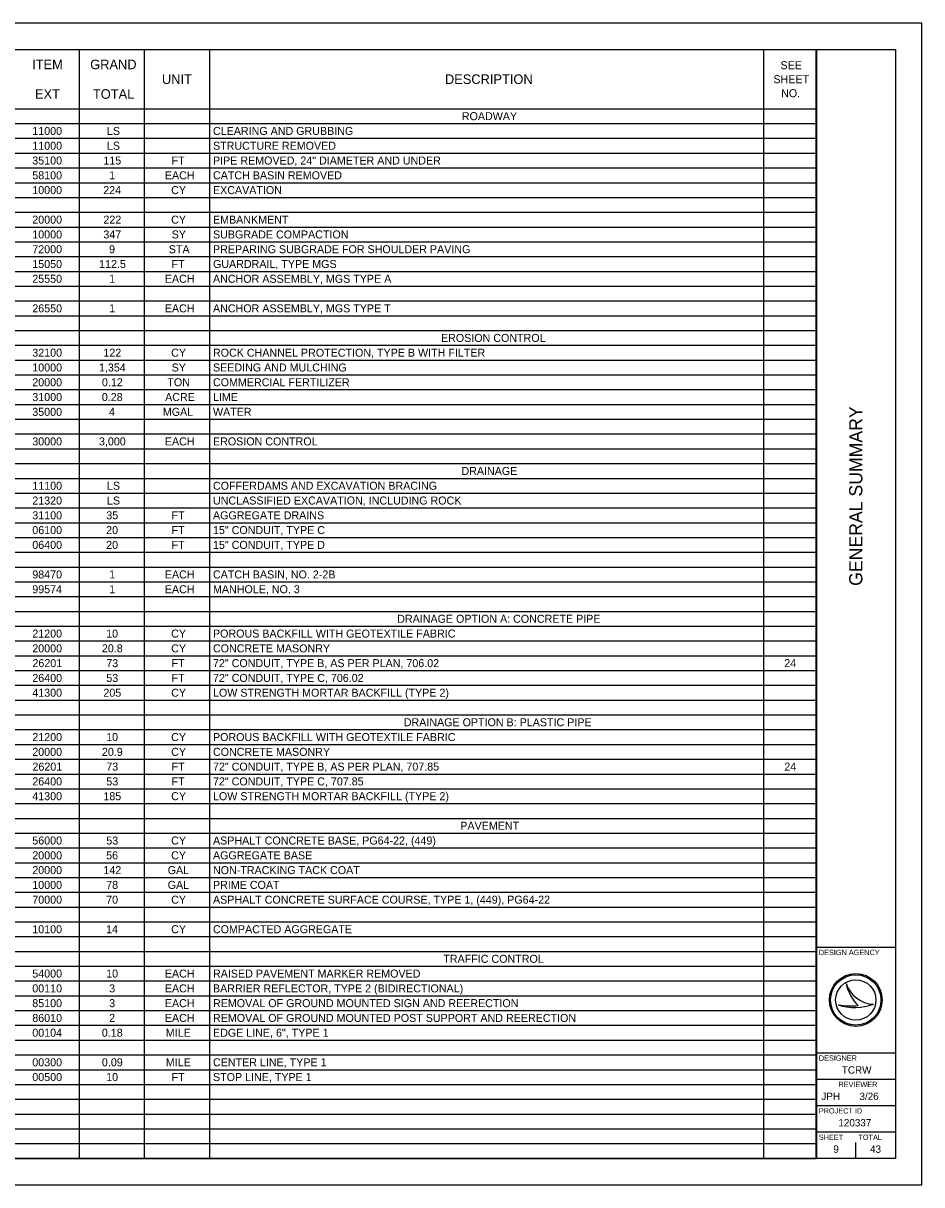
# Model space of a CAD drawing. Extents: x 0 to 34, y 0 to 35.
# Drawn here: x 16.98 to 34, y 0 to 22 of the extents above; entities that cross this region are included whole.
import ezdxf

# ---------------------------------------------------------------- set-up
doc = ezdxf.new("R2010")
doc.units = 0
for name, color, linetype in [('SH_Border', 7, 'Continuous'), ('SH_Cut_Line', 7, 'Continuous'), ('SH_Data', 7, 'Continuous'), ('SH_Text', 7, 'Continuous')]:
    doc.layers.add(name, color=color, linetype=linetype)

msp = doc.modelspace()

# ---------------------------------------------------------------- linework, layer by layer
at = {"layer": 'SH_Border'}
for p, q in [((32, 0.5), (32, 21.5)), ((32, 4.5), (33.5, 4.5)), ((32, 2.5), (33.5, 2.5)), ((32, 2), (33.5, 2)), ((32, 1.5), (33.5, 1.5)), ((32, 1), (33.5, 1))]:
    msp.add_line(p, q, dxfattribs=at)
msp.add_lwpolyline([(1.5, 21.5), (33.5, 21.5), (33.5, 0.5), (1.5, 0.5)], close=True, dxfattribs=at)
at = {"layer": 'SH_Cut_Line'}
msp.add_lwpolyline([(0, 0), (34, 0), (34, 22), (0, 22)], close=True, dxfattribs=at)
at = {"layer": 'SH_Data'}
for p, q in [((32.567, 3.81), (32.567, 3.81)), ((32.417, 3.41), (32.417, 3.41)), ((32.75, 3.5), (32.75, 3.5)), ((33.087, 3.419), (33.087, 3.419)), ((32.375, 0.675), (32.375, 0.675)), ((32.75, 0.5), (32.75, 0.8))]:
    msp.add_line(p, q, dxfattribs=at)
for radius in [0.5, 0.477, 0.477, 0.382]:
    msp.add_circle((32.75, 3.5), radius, dxfattribs=at)
for centre, radius, start, end in [((33.116, 3.998), 0.58, 198.9257, 198.9319), ((33.347, 3.97), 0.796, 191.6379, 191.6421), ((33.116, 3.998), 0.58, 198.9319, 267.1657), ((33.347, 3.97), 0.796, 191.6421, 226.0947), ((32.739, 4.37), 1.013, 251.4576, 290.0832), ((32.648, 4.654), 1.266, 259.4964, 259.4995), ((32.739, 4.37), 1.013, 251.4527, 251.4576), ((32.648, 4.654), 1.266, 259.4995, 276.6672)]:
    msp.add_arc(centre, radius, start, end, dxfattribs=at)
at = {"layer": 'SH_Text'}
for p, q in [((1.5, 21.5), (32.004, 21.5)), ((1.5, 21.5), (32.004, 21.5)), ((18.036, 21.5), (18.036, 0.5)), ((19.272, 21.5), (19.272, 0.5)), ((20.507, 21.5), (20.507, 0.5)), ((30.999, 21.5), (30.999, 0.5)), ((32.004, 21.5), (32.004, 0.5)), ((32.004, 21.5), (32.004, 0.5)), ((1.5, 20.38), (32.004, 20.38)), ((1.5, 20.1), (32.004, 20.1)), ((1.5, 19.82), (32.004, 19.82)), ((1.5, 19.54), (32.004, 19.54)), ((1.5, 19.26), (32.004, 19.26)), ((1.5, 18.98), (32.004, 18.98)), ((1.5, 18.7), (32.004, 18.7)), ((1.5, 18.42), (32.004, 18.42)), ((1.5, 18.14), (32.004, 18.14)), ((1.5, 17.86), (32.004, 17.86)), ((1.5, 17.58), (32.004, 17.58)), ((1.5, 17.3), (32.004, 17.3)), ((1.5, 17.02), (32.004, 17.02)), ((1.5, 16.74), (32.004, 16.74)), ((1.5, 16.46), (32.004, 16.46)), ((1.5, 16.18), (32.004, 16.18)), ((1.5, 15.9), (32.004, 15.9)), ((1.5, 15.62), (32.004, 15.62)), ((1.5, 15.34), (32.004, 15.34)), ((1.5, 15.06), (32.004, 15.06)), ((1.5, 14.78), (32.004, 14.78)), ((1.5, 14.5), (32.004, 14.5)), ((1.5, 14.22), (32.004, 14.22)), ((1.5, 13.94), (32.004, 13.94)), ((1.5, 13.66), (32.004, 13.66)), ((1.5, 13.38), (32.004, 13.38)), ((1.5, 13.1), (32.004, 13.1)), ((1.5, 12.82), (32.004, 12.82)), ((1.5, 12.54), (32.004, 12.54)), ((1.5, 12.26), (32.004, 12.26)), ((1.5, 11.98), (32.004, 11.98)), ((1.5, 11.7), (32.004, 11.7)), ((1.5, 11.42), (32.004, 11.42)), ((1.5, 11.14), (32.004, 11.14)), ((1.5, 10.86), (32.004, 10.86)), ((1.5, 10.58), (32.004, 10.58)), ((1.5, 10.3), (32.004, 10.3)), ((1.5, 10.02), (32.004, 10.02)), ((1.5, 9.74), (32.004, 9.74)), ((1.5, 9.46), (32.004, 9.46)), ((1.5, 9.18), (32.004, 9.18)), ((1.5, 8.9), (32.004, 8.9)), ((1.5, 8.62), (32.004, 8.62)), ((1.5, 8.34), (32.004, 8.34)), ((1.5, 8.06), (32.004, 8.06)), ((1.5, 7.78), (32.004, 7.78)), ((1.5, 7.5), (32.004, 7.5)), ((1.5, 7.22), (32.004, 7.22)), ((1.5, 6.94), (32.004, 6.94)), ((1.5, 6.66), (32.004, 6.66)), ((1.5, 6.38), (32.004, 6.38)), ((1.5, 6.1), (32.004, 6.1)), ((1.5, 5.82), (32.004, 5.82)), ((1.5, 5.54), (32.004, 5.54)), ((1.5, 5.26), (32.004, 5.26)), ((1.5, 4.98), (32.004, 4.98)), ((1.5, 4.7), (32.004, 4.7)), ((1.5, 4.42), (32.004, 4.42)), ((1.5, 4.14), (32.004, 4.14)), ((1.5, 3.86), (32.004, 3.86)), ((1.5, 3.58), (32.004, 3.58)), ((1.5, 3.3), (32.004, 3.3)), ((1.5, 3.02), (32.004, 3.02)), ((1.5, 2.74), (32.004, 2.74)), ((1.5, 2.46), (32.004, 2.46)), ((1.5, 2.18), (32.004, 2.18)), ((1.5, 1.9), (32.004, 1.9)), ((1.5, 1.62), (32.004, 1.62)), ((1.5, 1.34), (32.004, 1.34)), ((1.5, 1.06), (32.004, 1.06)), ((1.5, 0.78), (32.004, 0.78)), ((1.5, 0.5), (32.004, 0.5)), ((1.5, 0.5), (32.004, 0.5))]:
    msp.add_line(p, q, dxfattribs=at)

# ---------------------------------------------------------------- texts
at = {"layer": 'SH_Data'}
msp.add_text('GENERAL SUMMARY', height=0.25, rotation=90, dxfattribs=at).set_placement((32.875, 11.344))
for s, height, p in [('DESIGN AGENCY', 0.1, (32.05, 4.35)), ('DESIGNER', 0.1, (32.05, 2.35)), ('TCRW', 0.14, (32.486, 2.105)), ('REVIEWER', 0.1, (32.422, 1.85)), ('JPH', 0.14, (32.098, 1.605)), ('3/26', 0.14, (32.819, 1.605)), ('PROJECT ID', 0.1, (32.05, 1.35)), ('120337', 0.14, (32.42, 1.105)), ('SHEET', 0.1, (32.05, 0.85)), ('TOTAL', 0.1, (32.8, 0.85)), ('9', 0.14, (32.325, 0.605)), ('43', 0.14, (33.02, 0.605))]:
    msp.add_text(s, height=height, dxfattribs=at).set_placement(p)
at = {"layer": 'SH_Text'}
for s, height, p in [('ITEM', 0.1818, (17.147, 21.129)), ('GRAND', 0.1818, (18.247, 21.129)), ('SEE ', 0.1515, (31.324, 21.129)), ('UNIT', 0.1818, (19.606, 20.849)), ('DESCRIPTION', 0.18184, (24.967, 20.849)), ('SHEET ', 0.1515, (31.19, 20.864)), ('EXT', 0.1818, (17.201, 20.569)), ('TOTAL', 0.1818, (18.299, 20.569)), ('NO.', 0.1515, (31.335, 20.599)), ('ROADWAY', 0.1515, (25.287, 20.164)), ('11000', 0.1515, (17.15, 19.884)), ('LS', 0.1515, (18.564, 19.884)), ('CLEARING AND GRUBBING', 0.15153, (20.573, 19.884)), ('11000', 0.1515, (17.15, 19.604)), ('LS', 0.1515, (18.564, 19.604)), ('STRUCTURE REMOVED', 0.15153, (20.573, 19.604)), ('35100', 0.1515, (17.15, 19.324)), ('115', 0.1515, (18.497, 19.324)), ('FT', 0.1515, (19.789, 19.324)), ('PIPE REMOVED, 24" DIAMETER AND UNDER', 0.15153, (20.573, 19.324)), ('58100', 0.1515, (17.15, 19.044)), ('1', 0.152, (18.606, 19.044)), ('EACH', 0.1515, (19.661, 19.044)), ('CATCH BASIN REMOVED', 0.15153, (20.573, 19.044)), ('10000', 0.1515, (17.15, 18.764)), ('224', 0.1515, (18.494, 18.764)), ('CY', 0.1515, (19.781, 18.764)), ('EXCAVATION', 0.1515, (20.573, 18.764)), ('20000', 0.1515, (17.15, 18.204)), ('222', 0.1515, (18.497, 18.204)), ('CY', 0.1515, (19.781, 18.204)), ('EMBANKMENT', 0.1515, (20.573, 18.204)), ('10000', 0.1515, (17.15, 17.924)), ('347', 0.1515, (18.496, 17.924)), ('SY', 0.1515, (19.79, 17.924)), ('SUBGRADE COMPACTION', 0.15153, (20.573, 17.924)), ('72000', 0.1515, (17.15, 17.644)), ('9', 0.152, (18.605, 17.644)), ('STA', 0.1515, (19.736, 17.644)), ('PREPARING SUBGRADE FOR SHOULDER PAVING', 0.15153, (20.573, 17.644)), ('15050', 0.1515, (17.15, 17.364)), ('112.5', 0.1515, (18.416, 17.364)), ('FT', 0.1515, (19.789, 17.364)), ('GUARDRAIL, TYPE MGS', 0.15153, (20.573, 17.364)), ('25550', 0.1515, (17.15, 17.084)), ('1', 0.152, (18.606, 17.084)), ('EACH', 0.1515, (19.661, 17.084)), ('ANCHOR ASSEMBLY, MGS TYPE A', 0.15153, (20.573, 17.084)), ('26550', 0.1515, (17.15, 16.524)), ('1', 0.152, (18.606, 16.524)), ('EACH', 0.1515, (19.661, 16.524)), ('ANCHOR ASSEMBLY, MGS TYPE T', 0.15153, (20.573, 16.524)), ('EROSION CONTROL', 0.15153, (24.892, 15.964)), ('32100', 0.1515, (17.15, 15.684)), ('122', 0.1515, (18.497, 15.684)), ('CY', 0.1515, (19.781, 15.684)), ('ROCK CHANNEL PROTECTION, TYPE B WITH FILTER', 0.15153, (20.573, 15.684)), ('10000', 0.1515, (17.15, 15.404)), ('1,354', 0.1515, (18.413, 15.404)), ('SY', 0.1515, (19.79, 15.404)), ('SEEDING AND MULCHING', 0.15153, (20.573, 15.404)), ('20000', 0.1515, (17.15, 15.124)), ('0.12', 0.1515, (18.47, 15.124)), ('TON', 0.1515, (19.709, 15.124)), ('COMMERCIAL FERTILIZER', 0.15153, (20.573, 15.124)), ('31000', 0.1515, (17.15, 14.844)), ('0.28', 0.1515, (18.468, 14.844)), ('ACRE', 0.1515, (19.666, 14.844)), ('LIME', 0.1515, (20.573, 14.844)), ('35000', 0.1515, (17.15, 14.564)), ('4', 0.152, (18.603, 14.564)), ('MGAL', 0.1515, (19.623, 14.564)), ('WATER', 0.1515, (20.573, 14.564)), ('30000', 0.1515, (17.15, 14.004)), ('3,000', 0.1515, (18.413, 14.004)), ('EACH', 0.1515, (19.661, 14.004)), ('EROSION CONTROL', 0.15153, (20.573, 14.004)), ('DRAINAGE', 0.1515, (25.28, 13.444)), ('11100', 0.1515, (17.15, 13.164)), ('LS', 0.1515, (18.564, 13.164)), ('COFFERDAMS AND EXCAVATION BRACING', 0.15153, (20.573, 13.164)), ('21320', 0.1515, (17.15, 12.884)), ('LS', 0.1515, (18.564, 12.884)), ('UNCLASSIFIED EXCAVATION, INCLUDING ROCK', 0.15153, (20.573, 12.884)), ('31100', 0.1515, (17.15, 12.604)), ('35', 0.1515, (18.552, 12.604)), ('FT', 0.1515, (19.789, 12.604)), ('AGGREGATE DRAINS', 0.15153, (20.573, 12.604)), ('06100', 0.1515, (17.15, 12.324)), ('20', 0.1515, (18.549, 12.324)), ('FT', 0.1515, (19.789, 12.324)), ('15" CONDUIT, TYPE C', 0.15153, (20.573, 12.324)), ('06400', 0.1515, (17.15, 12.044)), ('20', 0.1515, (18.549, 12.044)), ('FT', 0.1515, (19.789, 12.044)), ('15" CONDUIT, TYPE D', 0.15153, (20.573, 12.044)), ('98470', 0.1515, (17.15, 11.484)), ('1', 0.152, (18.606, 11.484)), ('EACH', 0.1515, (19.661, 11.484)), ('CATCH BASIN, NO. 2-2B', 0.15153, (20.573, 11.484)), ('99574', 0.1515, (17.15, 11.204)), ('1', 0.152, (18.606, 11.204)), ('EACH', 0.1515, (19.661, 11.204)), ('MANHOLE, NO. 3', 0.15153, (20.573, 11.204)), ('DRAINAGE OPTION A: CONCRETE PIPE', 0.15153, (24.063, 10.644)), ('21200', 0.1515, (17.15, 10.364)), ('10', 0.1515, (18.549, 10.364)), ('CY', 0.1515, (19.781, 10.364)), ('POROUS BACKFILL WITH GEOTEXTILE FABRIC', 0.15153, (20.573, 10.364)), ('20000', 0.1515, (17.15, 10.084)), ('20.8', 0.1515, (18.468, 10.084)), ('CY', 0.1515, (19.781, 10.084)), ('CONCRETE MASONRY', 0.15153, (20.573, 10.084)), ('26201', 0.1515, (17.153, 9.804)), ('73', 0.1515, (18.552, 9.804)), ('FT', 0.1515, (19.789, 9.804)), ('72" CONDUIT, TYPE B, AS PER PLAN, 706.02', 0.15153, (20.573, 9.804)), ('24', 0.1515, (31.395, 9.804)), ('26400', 0.1515, (17.15, 9.524)), ('53', 0.1515, (18.552, 9.524)), ('FT', 0.1515, (19.789, 9.524)), ('72" CONDUIT, TYPE C, 706.02', 0.15153, (20.573, 9.524)), ('41300', 0.1515, (17.15, 9.244)), ('205', 0.1515, (18.497, 9.244)), ('CY', 0.1515, (19.781, 9.244)), ('LOW STRENGTH MORTAR BACKFILL (TYPE 2)', 0.15153, (20.573, 9.244)), ('DRAINAGE OPTION B: PLASTIC PIPE', 0.15153, (24.187, 8.684)), ('21200', 0.1515, (17.15, 8.404)), ('10', 0.1515, (18.549, 8.404)), ('CY', 0.1515, (19.781, 8.404)), ('POROUS BACKFILL WITH GEOTEXTILE FABRIC', 0.15153, (20.573, 8.404)), ('20000', 0.1515, (17.15, 8.124)), ('20.9', 0.1515, (18.469, 8.124)), ('CY', 0.1515, (19.781, 8.124)), ('CONCRETE MASONRY', 0.15153, (20.573, 8.124)), ('26201', 0.1515, (17.153, 7.844)), ('73', 0.1515, (18.552, 7.844)), ('FT', 0.1515, (19.789, 7.844)), ('72" CONDUIT, TYPE B, AS PER PLAN, 707.85', 0.15153, (20.573, 7.844)), ('24', 0.1515, (31.395, 7.844)), ('26400', 0.1515, (17.15, 7.564)), ('53', 0.1515, (18.552, 7.564)), ('FT', 0.1515, (19.789, 7.564)), ('72" CONDUIT, TYPE C, 707.85', 0.15153, (20.573, 7.564)), ('41300', 0.1515, (17.15, 7.284)), ('185', 0.1515, (18.497, 7.284)), ('CY', 0.1515, (19.781, 7.284)), ('LOW STRENGTH MORTAR BACKFILL (TYPE 2)', 0.15153, (20.573, 7.284)), ('PAVEMENT', 0.1515, (25.258, 6.724)), ('ASPHALT CONCRETE BASE, PG64-22, (449)', 0.15153, (20.573, 6.444)), ('56000', 0.1515, (17.15, 6.444)), ('53', 0.1515, (18.552, 6.444)), ('CY', 0.1515, (19.781, 6.444)), ('20000', 0.1515, (17.15, 6.164)), ('56', 0.1515, (18.549, 6.164)), ('CY', 0.1515, (19.781, 6.164)), ('AGGREGATE BASE', 0.15153, (20.573, 6.164)), ('20000', 0.1515, (17.15, 5.884)), ('142', 0.1515, (18.497, 5.884)), ('GAL', 0.1515, (19.715, 5.884)), ('NON-TRACKING TACK COAT', 0.15153, (20.573, 5.884)), ('10000', 0.1515, (17.15, 5.604)), ('78', 0.1515, (18.55, 5.604)), ('GAL', 0.1515, (19.715, 5.604)), ('PRIME COAT', 0.1515, (20.573, 5.604)), ('70000', 0.1515, (17.15, 5.324)), ('70', 0.1515, (18.549, 5.324)), ('CY', 0.1515, (19.781, 5.324)), ('ASPHALT CONCRETE SURFACE COURSE, TYPE 1, (449), PG64-22', 0.15153, (20.573, 5.324)), ('10100', 0.1515, (17.15, 4.764)), ('14', 0.1515, (18.548, 4.764)), ('CY', 0.1515, (19.781, 4.764)), ('COMPACTED AGGREGATE', 0.15153, (20.573, 4.764)), ('TRAFFIC CONTROL', 0.15153, (24.936, 4.204)), ('54000', 0.1515, (17.15, 3.924)), ('10', 0.1515, (18.549, 3.924)), ('EACH', 0.1515, (19.661, 3.924)), ('RAISED PAVEMENT MARKER REMOVED', 0.15153, (20.573, 3.924)), ('00110', 0.1515, (17.15, 3.644)), ('3', 0.152, (18.606, 3.644)), ('EACH', 0.1515, (19.661, 3.644)), ('BARRIER REFLECTOR, TYPE 2 (BIDIRECTIONAL)', 0.15153, (20.573, 3.644)), ('85100', 0.1515, (17.15, 3.364)), ('3', 0.152, (18.606, 3.364)), ('EACH', 0.1515, (19.661, 3.364)), ('REMOVAL OF GROUND MOUNTED SIGN AND REERECTION', 0.15153, (20.573, 3.364)), ('86010', 0.1515, (17.15, 3.084)), ('2', 0.152, (18.606, 3.084)), ('EACH', 0.1515, (19.661, 3.084)), ('REMOVAL OF GROUND MOUNTED POST SUPPORT AND REERECTION', 0.15153, (20.573, 3.084)), ('00104', 0.1515, (17.15, 2.804)), ('0.18', 0.1515, (18.468, 2.804)), ('MILE', 0.1515, (19.679, 2.804)), ('EDGE LINE, 6", TYPE 1', 0.15153, (20.573, 2.804)), ('00300', 0.1515, (17.15, 2.244)), ('0.09', 0.1515, (18.469, 2.244)), ('MILE', 0.1515, (19.679, 2.244)), ('CENTER LINE, TYPE 1', 0.15153, (20.573, 2.244)), ('00500', 0.1515, (17.15, 1.964)), ('10', 0.1515, (18.549, 1.964)), ('FT', 0.1515, (19.789, 1.964)), ('STOP LINE, TYPE 1', 0.15153, (20.573, 1.964))]:
    msp.add_text(s, height=height, dxfattribs=at).set_placement(p)

doc.saveas('drawing.dxf')
